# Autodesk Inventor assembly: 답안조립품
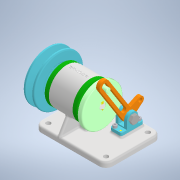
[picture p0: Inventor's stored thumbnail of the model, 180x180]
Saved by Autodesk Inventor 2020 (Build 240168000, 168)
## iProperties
Created: 2021-06
Part Number: 답안조립품
Document SubType Name: Assembly
Designer: 301-08
Mass: 1409.71 g
Surface Area: 1436.04 cm^2
Volume: 422.068 cm^3
Density: 3.34 g/cm^3
Author: 301-08
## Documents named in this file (20)
- C:\Users\301-08\Desktop\610606V1037\답안조립품.iam
- C:\Users\301-08\Desktop\610606V1037\본체.ipt
- C:\Users\301-08\Desktop\610606V1037\돌림판.ipt
- C:\Users\301-08\Desktop\610606V1037\멈춤나사 M3x5.ipt
- C:\Users\301-08\Desktop\610606V1037\베어링 6004.ipt
- C:\Users\301-08\Desktop\610606V1037\볼트 M4.ipt
- C:\Users\301-08\Desktop\610606V1037\오일 실 17 30 5.ipt
- C:\Users\301-08\Desktop\610606V1037\축.ipt
- C:\Users\301-08\Desktop\610606V1037\커버.ipt
- C:\Users\301-08\Desktop\610606V1037\키 4 x 4 x 8.ipt
- C:\Users\301-08\Desktop\610606V1037\키 5 x 5 x 12.ipt
- C:\Users\301-08\Desktop\610606V1037\V-벨트풀리.ipt
- C:\Users\301-08\Desktop\610606V1037\너트 M10x1.ipt
- C:\Users\301-08\Desktop\610606V1037\와셔 10x18.ipt
- C:\Users\301-08\Desktop\610606V1037\너트 M8.ipt
- C:\Users\301-08\Desktop\610606V1037\와셔 8x15.5.ipt
- C:\Users\301-08\Desktop\610606V1037\크랭크.ipt
- C:\Users\301-08\Desktop\610606V1037\핀 3 x 8.ipt
- C:\Users\301-08\Desktop\610606V1037\힌지 축.ipt
- C:\Users\301-08\Desktop\610606V1037\힌지.ipt
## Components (3 placed, 2 different names)
1. V-벨트풀리:1
2. 핀 3 x 8:1
3. 핀 3 x 8:2
